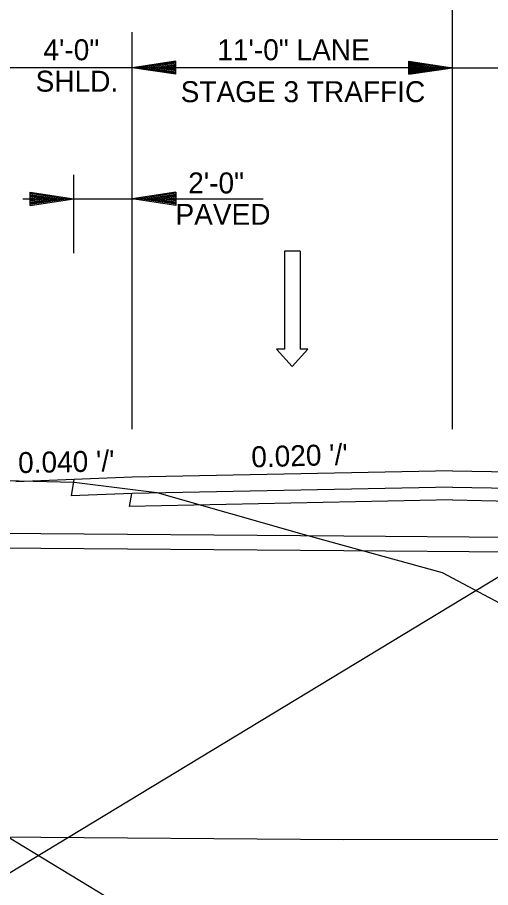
# Model space of a CAD drawing. Extents: x 1807779 to 1818251, y 673292 to 678849.
# Drawn here: x 1817121.9 to 1817284.3, y 673780.7 to 674079.8 of the extents above; entities that cross this region are included whole.
import ezdxf

# ---------------------------------------------------------------- set-up
doc = ezdxf.new("R2010")
doc.units = 0
for name, color, linetype in [('Default', 7, 'Continuous'), ('Dimensions', 7, 'Continuous'), ('S_PHOTO_CTL_ANNOT', 7, 'Continuous'), ('T_Drafting', 7, 'Continuous')]:
    doc.layers.add(name, color=color, linetype=linetype)

msp = doc.modelspace()

# ---------------------------------------------------------------- linework, layer by layer
at = {"layer": 'Default'}
for p, q in [((1817271.27, 673923.97), (1817381.27, 673921.77)), ((1817141.28, 673920.98), (1817140.35, 673915.37)), ((1817271.27, 673918.4), (1817381.27, 673916.2)), ((1817160.99, 673916.19), (1817160.25, 673911.75)), ((1817271.27, 673913.97), (1817160.25, 673911.75)), ((1817271.27, 673913.97), (1817381.27, 673911.77)), ((1817233.94, 673901.46), (1817028.21, 673903.04)), ((1817525.2, 673899.23), (1817233.94, 673901.46)), ((1817233.94, 673896.46), (1817028.21, 673898.04)), ((1817525.2, 673894.23), (1817233.94, 673896.46)), ((1817233.94, 673797.12), (1816767.98, 673800.7)), ((1817809.49, 673798.22), (1817233.94, 673797.12))]:
    msp.add_line(p, q, dxfattribs=at)
for points in [[(1817271.27, 673923.97), (1817161.27, 673921.77), (1817121.3, 673920.18)], [(1817271.27, 673918.4), (1817161.27, 673916.2), (1817140.35, 673915.37)]]:
    msp.add_lwpolyline(points, dxfattribs=at)
at = {"layer": 'Dimensions'}
for p, q in [((1817271.27, 673938.29), (1817271.27, 674149.46)), ((1817161.23, 673938.29), (1817161.23, 674074.68)), ((1817176.23, 674064.76), (1817161.23, 674062.51)), ((1817176.23, 674060.26), (1817176.23, 674064.76)), ((1817256.23, 674064.76), (1817271.23, 674062.51)), ((1817256.23, 674060.26), (1817256.23, 674064.76)), ((1817256.27, 674064.73), (1817271.27, 674062.48)), ((1817256.27, 674064.73), (1817256.27, 674060.23)), ((1817161.23, 674062.51), (1817101.36, 674062.51)), ((1817271.23, 674062.51), (1817161.23, 674062.51)), ((1817176.23, 674060.26), (1817161.23, 674062.51)), ((1817176.23, 674064.38), (1817163.73, 674062.51)), ((1817176.23, 674060.63), (1817163.73, 674062.51)), ((1817176.23, 674064), (1817166.31, 674062.51)), ((1817176.23, 674061.02), (1817166.31, 674062.51)), ((1817176.23, 674063.63), (1817168.81, 674062.51)), ((1817176.23, 674061.39), (1817168.81, 674062.51)), ((1817176.23, 674063.24), (1817171.35, 674062.51)), ((1817176.23, 674061.78), (1817171.35, 674062.51)), ((1817176.23, 674062.86), (1817173.86, 674062.51)), ((1817176.23, 674062.16), (1817173.86, 674062.51)), ((1817271.23, 674062.51), (1817211.8, 674062.51)), ((1817256.23, 674064.38), (1817268.72, 674062.51)), ((1817256.23, 674064), (1817266.14, 674062.51)), ((1817256.23, 674063.63), (1817263.65, 674062.51)), ((1817256.23, 674063.24), (1817261.1, 674062.51)), ((1817256.23, 674062.86), (1817258.6, 674062.51)), ((1817256.23, 674060.26), (1817271.23, 674062.51)), ((1817256.23, 674061.78), (1817261.1, 674062.51)), ((1817256.23, 674061.02), (1817266.14, 674062.51)), ((1817256.23, 674060.63), (1817268.72, 674062.51)), ((1817256.23, 674061.39), (1817263.65, 674062.51)), ((1817256.23, 674062.16), (1817258.6, 674062.51)), ((1817256.27, 674064.35), (1817268.76, 674062.48)), ((1817256.27, 674063.97), (1817266.18, 674062.48)), ((1817256.27, 674063.6), (1817263.68, 674062.48)), ((1817256.27, 674063.21), (1817261.14, 674062.48)), ((1817256.27, 674062.83), (1817258.64, 674062.48)), ((1817256.27, 674060.23), (1817271.27, 674062.48)), ((1817256.27, 674061.74), (1817261.14, 674062.48)), ((1817256.27, 674060.99), (1817266.18, 674062.48)), ((1817256.27, 674060.6), (1817268.76, 674062.48)), ((1817256.27, 674061.36), (1817263.68, 674062.48)), ((1817256.27, 674062.13), (1817258.64, 674062.48)), ((1817271.27, 674062.51), (1817381.27, 674062.51)), ((1817141.27, 673998.72), (1817141.27, 674025.65)), ((1817123.68, 674017.45), (1817206.22, 674017.45)), ((1817126.27, 674019.7), (1817141.27, 674017.45)), ((1817126.27, 674015.2), (1817126.27, 674019.7)), ((1817126.27, 674019.33), (1817138.76, 674017.45)), ((1817126.27, 674018.94), (1817136.18, 674017.45)), ((1817126.27, 674018.57), (1817133.68, 674017.45)), ((1817126.27, 674018.19), (1817131.14, 674017.45)), ((1817126.27, 674017.8), (1817128.64, 674017.45)), ((1817126.27, 674015.2), (1817141.27, 674017.45)), ((1817126.27, 674016.72), (1817131.14, 674017.45)), ((1817126.27, 674015.96), (1817136.18, 674017.45)), ((1817126.27, 674015.58), (1817138.76, 674017.45)), ((1817126.27, 674016.33), (1817133.68, 674017.45)), ((1817126.27, 674017.1), (1817128.64, 674017.45)), ((1817176.27, 674019.7), (1817161.27, 674017.45)), ((1817176.27, 674015.2), (1817161.27, 674017.45)), ((1817176.27, 674019.33), (1817163.77, 674017.45)), ((1817176.27, 674015.58), (1817163.77, 674017.45)), ((1817176.27, 674018.94), (1817166.35, 674017.45)), ((1817176.27, 674015.96), (1817166.35, 674017.45)), ((1817176.27, 674018.57), (1817168.85, 674017.45)), ((1817176.27, 674016.33), (1817168.85, 674017.45)), ((1817176.27, 674018.18), (1817171.39, 674017.45)), ((1817176.27, 674016.72), (1817171.39, 674017.45)), ((1817176.27, 674017.8), (1817173.9, 674017.45)), ((1817176.27, 674017.1), (1817173.9, 674017.45)), ((1817176.27, 674019.7), (1817176.27, 674015.2)), ((1817218.93, 673999.46), (1817218.93, 673965.74))]:
    msp.add_line(p, q, dxfattribs=at)
msp.add_lwpolyline([(1817218.93, 673999.46), (1817213.53, 673999.46), (1817213.53, 673965.74), (1817210.83, 673965.74), (1817216.23, 673959.81), (1817221.63, 673965.74), (1817218.93, 673965.74)], dxfattribs=at)
at = {"layer": 'S_PHOTO_CTL_ANNOT'}
for p, q in [((1816304.06, 674291.38), (1817954.06, 673292.32)), ((1816304.06, 673292.32), (1817954.06, 674291.38))]:
    msp.add_line(p, q, dxfattribs=at)
at = {"layer": 'T_Drafting'}
msp.add_lwpolyline([(1816332.56, 673916.49), (1816388.22, 673883.53), (1816523.6, 673790.73), (1816686.17, 673902.98), (1816727.67, 673909.74), (1816777.91, 673920.14), (1816872.77, 673921.8), (1816952.95, 673922.87), (1817112.95, 673920.73), (1817141.41, 673920.09), (1817169.75, 673916.5), (1817220.31, 673902.07), (1817267.77, 673888.98), (1817382.47, 673827.97), (1817459.92, 673810.13), (1817515.42, 673805.48), (1817571.86, 673800.64), (1817758.67, 673799.67), (1817826.35, 673802.24)], dxfattribs=at)

# ---------------------------------------------------------------- texts
at = {"layer": 'Dimensions'}
for s, p in [('4\'-0" ', (1817130.8, 674065.06)), ('11\'-0" LANE', (1817190.51, 674065.06)), ('SHLD. ', (1817128.11, 674054.26)), ('STAGE 3 TRAFFIC', (1817177.92, 674050.66)), ('2\'-0"', (1817180.52, 674019.3)), ('PAVED', (1817176.14, 674008.5))]:
    msp.add_text(s, height=7.2, dxfattribs=at).set_placement(p)
for s, rotation, p in [("0.020 '/'", 1.608, (1817202.28, 673925.13)), ("0.040 '/'", 1.1223, (1817122.17, 673923.16))]:
    msp.add_text(s, height=7.2, rotation=rotation, dxfattribs=at).set_placement(p)

doc.saveas('drawing.dxf')
